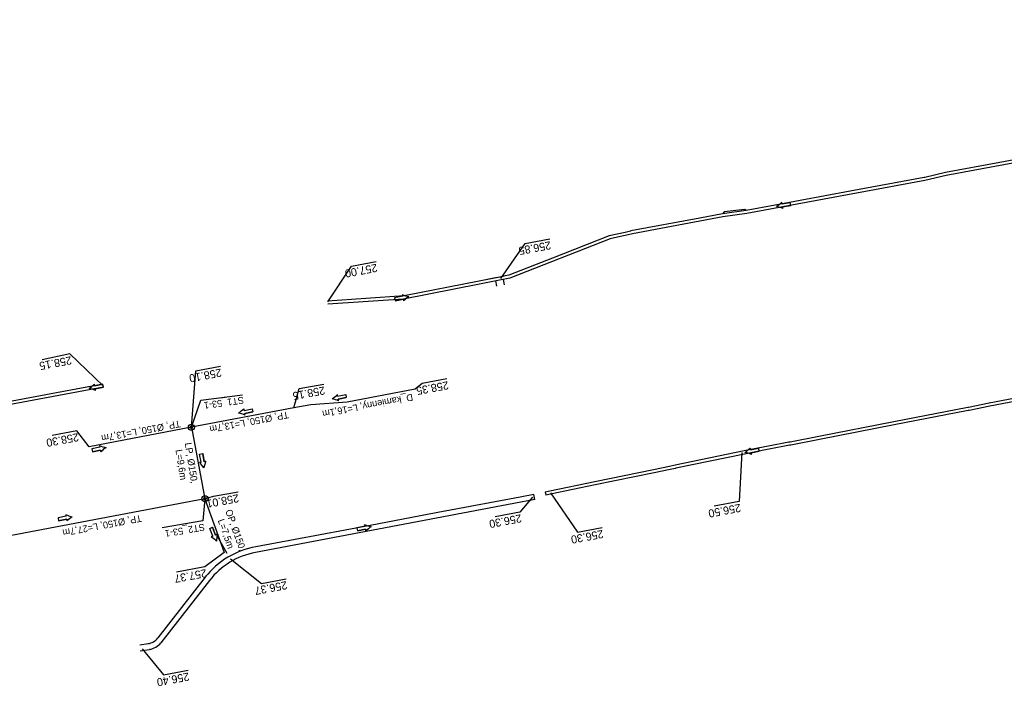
# Model space of a CAD drawing. Extents: x -1 to 65640748, y -22 to 5530284.
# Drawn here: x 6565167.7 to 6565296.8, y 5530114.9 to 5530202.4 of the extents above; entities that cross this region are included whole.
import ezdxf

# ---------------------------------------------------------------- set-up
doc = ezdxf.new("R2010")
doc.units = 0
for name, color, linetype in [('TOR_PS_ODW-drenaze', 7, 'Continuous'), ('TOR_PS_ODW-drenokolektory', 7, 'Continuous'), ('TOR_PS_ODW-kolektory', 7, 'Continuous'), ('TOR_PS_ODW-studnie PEHD', 7, 'Continuous'), ('TOR_PS_OPIS_O-opisy rurociagow', 7, 'Continuous'), ('TOR_PS_OPIS_O-opisy studni', 7, 'Continuous'), ('TOR_PS_OPIS_T-INFO', 7, 'Continuous'), ('TOR_PS_T-rowy otwarte umocnione', 7, 'Continuous')]:
    doc.layers.add(name, color=color, linetype=linetype)

msp = doc.modelspace()

# ---------------------------------------------------------------- linework, layer by layer
at = {"layer": 'TOR_PS_ODW-drenaze'}
for p, q in [((6565203.61, 5530151.46), (6565190.18, 5530148.92)), ((6565190.18, 5530148.92), (6565176.76, 5530146.37))]:
    msp.add_line(p, q, dxfattribs=at)
for points in [[(6565219.54, 5530153.92), (6565210.6, 5530152.23), (6565205.84, 5530151.88), (6565203.61, 5530151.46)], [(6565191.96, 5530139.54), (6565164.7, 5530134.37)]]:
    msp.add_lwpolyline(points, dxfattribs=at)
at = {"layer": 'TOR_PS_ODW-drenokolektory'}
msp.add_lwpolyline([(6565190.18, 5530148.92), (6565191.96, 5530139.54)], dxfattribs=at)
at = {"layer": 'TOR_PS_ODW-kolektory'}
msp.add_line((6565191.96, 5530139.54), (6565194.47, 5530132.49), dxfattribs=at)
at = {"layer": 'TOR_PS_ODW-studnie PEHD'}
for centre, radius in [((6565190.18, 5530148.92), 0.4), ((6565190.18, 5530148.92), 0.145), ((6565191.96, 5530139.54), 0.4), ((6565191.96, 5530139.54), 0.145)]:
    msp.add_circle(centre, radius, dxfattribs=at)
at = {"layer": 'TOR_PS_OPIS_O-opisy rurociagow'}
for p, q in [((6565268.71, 5530178.42), (6565267.64, 5530178.22)), ((6565267.64, 5530178.22), (6565268.71, 5530178.42)), ((6565267.71, 5530177.83), (6565268.78, 5530178.03)), ((6565267.71, 5530177.83), (6565268.78, 5530178.03)), ((6565268.78, 5530178.03), (6565268.71, 5530178.42)), ((6565268.78, 5530178.03), (6565268.71, 5530178.42)), ((6565217.9, 5530166.12), (6565216.83, 5530165.9)), ((6565217.9, 5530166.12), (6565216.83, 5530165.9)), ((6565216.83, 5530165.9), (6565216.91, 5530165.51)), ((6565216.83, 5530165.9), (6565216.91, 5530165.51)), ((6565216.91, 5530165.51), (6565217.98, 5530165.72)), ((6565217.98, 5530165.72), (6565216.91, 5530165.51)), ((6565178.56, 5530154.56), (6565177.49, 5530154.36)), ((6565177.49, 5530154.36), (6565178.56, 5530154.56)), ((6565177.56, 5530153.97), (6565178.64, 5530154.16)), ((6565177.56, 5530153.97), (6565178.64, 5530154.16)), ((6565178.64, 5530154.16), (6565178.56, 5530154.56)), ((6565178.64, 5530154.16), (6565178.56, 5530154.56)), ((6565209.35, 5530152.99), (6565210.43, 5530153.2)), ((6565209.35, 5530152.99), (6565210.43, 5530153.2)), ((6565210.5, 5530152.81), (6565209.43, 5530152.6)), ((6565209.43, 5530152.6), (6565210.5, 5530152.81)), ((6565210.43, 5530153.2), (6565210.5, 5530152.81)), ((6565210.43, 5530153.2), (6565210.5, 5530152.81)), ((6565197.09, 5530151.13), (6565198.16, 5530151.35)), ((6565197.09, 5530151.13), (6565198.16, 5530151.35)), ((6565198.24, 5530150.96), (6565197.17, 5530150.74)), ((6565197.17, 5530150.74), (6565198.24, 5530150.96)), ((6565198.16, 5530151.35), (6565198.24, 5530150.96)), ((6565198.16, 5530151.35), (6565198.24, 5530150.96)), ((6565178.19, 5530146.3), (6565177.12, 5530146.09)), ((6565178.19, 5530146.3), (6565177.12, 5530146.09)), ((6565177.12, 5530146.09), (6565177.19, 5530145.7)), ((6565177.12, 5530146.09), (6565177.19, 5530145.7)), ((6565177.19, 5530145.7), (6565178.26, 5530145.9)), ((6565178.26, 5530145.9), (6565177.19, 5530145.7)), ((6565191.26, 5530145.39), (6565191.66, 5530145.47)), ((6565191.26, 5530145.39), (6565191.66, 5530145.47)), ((6565191.47, 5530144.32), (6565191.26, 5530145.39)), ((6565191.47, 5530144.32), (6565191.26, 5530145.39)), ((6565191.66, 5530145.47), (6565191.86, 5530144.39)), ((6565191.86, 5530144.39), (6565191.66, 5530145.47)), ((6565264.58, 5530146.18), (6565263.5, 5530145.97)), ((6565263.5, 5530145.97), (6565264.58, 5530146.18)), ((6565263.58, 5530145.58), (6565264.65, 5530145.79)), ((6565263.58, 5530145.58), (6565264.65, 5530145.79)), ((6565264.65, 5530145.79), (6565264.58, 5530146.18)), ((6565264.65, 5530145.79), (6565264.58, 5530146.18)), ((6565173.76, 5530137.24), (6565172.69, 5530137.03)), ((6565173.76, 5530137.24), (6565172.69, 5530137.03)), ((6565172.69, 5530137.03), (6565172.76, 5530136.64)), ((6565172.69, 5530137.03), (6565172.76, 5530136.64)), ((6565172.76, 5530136.64), (6565173.83, 5530136.84)), ((6565173.83, 5530136.84), (6565172.76, 5530136.64)), ((6565212.95, 5530135.93), (6565211.88, 5530135.72)), ((6565212.95, 5530135.93), (6565211.88, 5530135.72)), ((6565192.58, 5530135.63), (6565192.95, 5530135.79)), ((6565192.58, 5530135.63), (6565192.95, 5530135.79)), ((6565192.99, 5530134.62), (6565192.58, 5530135.63)), ((6565192.99, 5530134.62), (6565192.58, 5530135.63)), ((6565192.95, 5530135.79), (6565193.36, 5530134.78)), ((6565193.36, 5530134.78), (6565192.95, 5530135.79)), ((6565211.88, 5530135.72), (6565211.95, 5530135.33)), ((6565211.88, 5530135.72), (6565211.95, 5530135.33)), ((6565211.95, 5530135.33), (6565213.03, 5530135.53)), ((6565213.03, 5530135.53), (6565211.95, 5530135.33))]:
    msp.add_line(p, q, dxfattribs=at)
for points in [[(6565267.61, 5530178.45), (6565267.61, 5530178.45)], [(6565267.76, 5530177.61), (6565267.76, 5530177.61)], [(6565217.85, 5530166.33), (6565217.85, 5530166.33)], [(6565218.01, 5530165.5), (6565218.01, 5530165.5)], [(6565177.46, 5530154.58), (6565177.46, 5530154.58)], [(6565177.61, 5530153.75), (6565177.61, 5530153.75)], [(6565209.32, 5530153.21), (6565209.32, 5530153.21)], [(6565209.49, 5530152.38), (6565209.49, 5530152.38)], [(6565197.05, 5530151.35), (6565197.05, 5530151.35)], [(6565197.22, 5530150.52), (6565197.22, 5530150.52)], [(6565178.14, 5530146.52), (6565178.14, 5530146.52)], [(6565178.3, 5530145.68), (6565178.3, 5530145.68)], [(6565263.47, 5530146.19), (6565263.47, 5530146.19)], [(6565263.63, 5530145.36), (6565263.63, 5530145.36)], [(6565191.25, 5530144.29), (6565191.25, 5530144.29)], [(6565192.08, 5530144.45), (6565192.08, 5530144.45)], [(6565173.71, 5530137.46), (6565173.71, 5530137.46)], [(6565173.87, 5530136.62), (6565173.87, 5530136.62)], [(6565212.9, 5530136.15), (6565212.9, 5530136.15)], [(6565193.56, 5530134.87), (6565193.56, 5530134.87)], [(6565213.06, 5530135.31), (6565213.06, 5530135.31)], [(6565192.78, 5530134.55), (6565192.78, 5530134.55)]]:
    msp.add_lwpolyline(points, dxfattribs=at)
for centre, radius, start, end in [((6565264.18, 5530181.97), 4.92, 303.8312, 314.213), ((6565264.18, 5530181.97), 4.92, 303.8312, 314.213), ((6565265.82, 5530173.09), 4.92, 66.7933, 77.1751), ((6565265.82, 5530173.09), 4.92, 66.7933, 77.1751), ((6565267.18, 5530178.28), 0.458, 353.6372, 22.0985), ((6565267.18, 5530178.28), 0.458, 353.6372, 22.0985), ((6565267.3, 5530177.62), 0.458, 358.9079, 27.3691), ((6565267.3, 5530177.62), 0.458, 358.9079, 27.3691), ((6565219.73, 5530170.88), 4.92, 247.4709, 257.8527), ((6565218.31, 5530166.33), 0.458, 179.5854, 208.0467), ((6565219.73, 5530170.88), 4.92, 247.4709, 257.8527), ((6565218.31, 5530166.33), 0.458, 179.5854, 208.0467), ((6565218.44, 5530165.68), 0.458, 174.3148, 202.776), ((6565218.44, 5530165.68), 0.458, 174.3148, 202.776), ((6565221.48, 5530162.02), 4.92, 124.5087, 134.8906), ((6565221.48, 5530162.02), 4.92, 124.5087, 134.8906), ((6565174.03, 5530158.11), 4.92, 303.8339, 314.2157), ((6565174.03, 5530158.11), 4.92, 303.8339, 314.2157), ((6565175.67, 5530149.23), 4.92, 66.796, 77.1778), ((6565175.67, 5530149.23), 4.92, 66.796, 77.1778), ((6565177.03, 5530154.41), 0.458, 353.6399, 22.1012), ((6565177.03, 5530154.41), 0.458, 353.6399, 22.1012), ((6565177.15, 5530153.75), 0.458, 358.9106, 27.3718), ((6565177.15, 5530153.75), 0.458, 358.9106, 27.3718), ((6565205.84, 5530156.68), 4.92, 304.7037, 315.0855), ((6565205.84, 5530156.68), 4.92, 304.7037, 315.0855), ((6565208.9, 5530153.03), 0.458, 354.5097, 22.9709), ((6565208.9, 5530153.03), 0.458, 354.5097, 22.9709), ((6565207.62, 5530147.83), 4.92, 67.6658, 78.0476), ((6565207.62, 5530147.83), 4.92, 67.6658, 78.0476), ((6565209.03, 5530152.38), 0.458, 359.7803, 28.2416), ((6565209.03, 5530152.38), 0.458, 359.7803, 28.2416), ((6565193.57, 5530154.83), 4.92, 304.7037, 315.0855), ((6565193.57, 5530154.83), 4.92, 304.7037, 315.0855), ((6565195.35, 5530145.97), 4.92, 67.6658, 78.0476), ((6565195.35, 5530145.97), 4.92, 67.6658, 78.0476), ((6565196.63, 5530151.18), 0.458, 354.5097, 22.9709), ((6565196.63, 5530151.18), 0.458, 354.5097, 22.9709), ((6565196.76, 5530150.52), 0.458, 359.7803, 28.2416), ((6565196.76, 5530150.52), 0.458, 359.7803, 28.2416), ((6565180.06, 5530151.04), 4.92, 247.0234, 257.4052), ((6565178.6, 5530146.51), 0.458, 179.1379, 207.5992), ((6565180.06, 5530151.04), 4.92, 247.0234, 257.4052), ((6565178.6, 5530146.51), 0.458, 179.1379, 207.5992), ((6565178.72, 5530145.86), 0.458, 173.8673, 202.3285), ((6565178.72, 5530145.86), 0.458, 173.8673, 202.3285), ((6565181.74, 5530142.17), 4.92, 124.0613, 134.4431), ((6565181.74, 5530142.17), 4.92, 124.0613, 134.4431), ((6565260.01, 5530149.69), 4.92, 304.3196, 314.7014), ((6565260.01, 5530149.69), 4.92, 304.3196, 314.7014), ((6565261.74, 5530140.82), 4.92, 67.2817, 77.6635), ((6565261.74, 5530140.82), 4.92, 67.2817, 77.6635), ((6565263.05, 5530146.02), 0.458, 354.1256, 22.5869), ((6565263.05, 5530146.02), 0.458, 354.1256, 22.5869), ((6565263.18, 5530145.36), 0.458, 359.3963, 27.8575), ((6565263.18, 5530145.36), 0.458, 359.3963, 27.8575), ((6565191.42, 5530143.86), 0.458, 84.0612, 112.5225), ((6565191.42, 5530143.86), 0.458, 84.0612, 112.5225), ((6565187.75, 5530140.83), 4.92, 34.2552, 44.637), ((6565187.75, 5530140.83), 4.92, 34.2552, 44.637), ((6565196.62, 5530142.54), 4.92, 157.2173, 167.5991), ((6565196.62, 5530142.54), 4.92, 157.2173, 167.5991), ((6565192.08, 5530143.99), 0.458, 89.3319, 117.7931), ((6565192.08, 5530143.99), 0.458, 89.3319, 117.7931), ((6565175.63, 5530141.98), 4.92, 247.0234, 257.4052), ((6565174.17, 5530137.45), 0.458, 179.1379, 207.5992), ((6565175.63, 5530141.98), 4.92, 247.0234, 257.4052), ((6565174.17, 5530137.45), 0.458, 179.1379, 207.5992), ((6565174.29, 5530136.8), 0.458, 173.8673, 202.3285), ((6565174.29, 5530136.8), 0.458, 173.8673, 202.3285), ((6565177.31, 5530133.11), 4.92, 124.0613, 134.4431), ((6565177.31, 5530133.11), 4.92, 124.0613, 134.4431), ((6565214.82, 5530140.67), 4.92, 246.9669, 257.3487), ((6565213.36, 5530136.14), 0.458, 179.0814, 207.5427), ((6565214.82, 5530140.67), 4.92, 246.9669, 257.3487), ((6565213.36, 5530136.14), 0.458, 179.0814, 207.5427), ((6565193.65, 5530134.42), 0.458, 100.7282, 129.1895), ((6565193.65, 5530134.42), 0.458, 100.7282, 129.1895), ((6565198.39, 5530133.9), 4.92, 168.6137, 178.9955), ((6565198.39, 5530133.9), 4.92, 168.6137, 178.9955), ((6565213.48, 5530135.48), 0.458, 173.8108, 202.272), ((6565213.48, 5530135.48), 0.458, 173.8108, 202.272), ((6565216.5, 5530131.8), 4.92, 124.0048, 134.3866), ((6565216.5, 5530131.8), 4.92, 124.0048, 134.3866), ((6565193.03, 5530134.17), 0.458, 95.4576, 123.9188), ((6565193.03, 5530134.17), 0.458, 95.4576, 123.9188), ((6565190.03, 5530130.47), 4.92, 45.6516, 56.0334), ((6565190.03, 5530130.47), 4.92, 45.6516, 56.0334)]:
    msp.add_arc(centre, radius, start, end, dxfattribs=at)
at = {"layer": 'TOR_PS_OPIS_T-INFO'}
for points in [[(6565230.77, 5530168.44), (6565233.96, 5530173.04), (6565237.2, 5530173.64)], [(6565208.07, 5530165.36), (6565211.19, 5530170.07), (6565214.42, 5530170.67)], [(6565178.6, 5530154.36), (6565174.24, 5530158.54), (6565170.59, 5530157.78)], [(6565190.18, 5530148.92), (6565190.76, 5530156.32), (6565194, 5530156.93)], [(6565203.61, 5530151.46), (6565204.33, 5530153.99), (6565207.56, 5530154.59)], [(6565223.68, 5530155.26), (6565223.68, 5530155.26), (6565220.45, 5530154.64), (6565219.54, 5530153.92)], [(6565190.18, 5530148.92), (6565191.4, 5530152.49), (6565196.9, 5530153.19)], [(6565176.76, 5530146.37), (6565175.17, 5530148.46), (6565171.93, 5530147.83)], [(6565262.36, 5530145.59), (6565262, 5530139.17), (6565258.76, 5530138.55)], [(6565191.96, 5530139.54), (6565193.1, 5530139.86), (6565196.33, 5530140.46)], [(6565237.27, 5530140.31), (6565240.83, 5530135.16), (6565244.07, 5530135.76)], [(6565191.96, 5530139.54), (6565191.66, 5530136.64), (6565186.35, 5530135.74)], [(6565234.9, 5530139.73), (6565233.25, 5530137.8), (6565230.01, 5530137.18)], [(6565194.47, 5530132.49), (6565191.96, 5530130.61), (6565188.21, 5530129.89)], [(6565195.32, 5530131.65), (6565199.36, 5530128.43), (6565202.59, 5530129.04)], [(6565183.71, 5530119.87), (6565186.51, 5530116.44), (6565189.75, 5530117.04)]]:
    msp.add_lwpolyline(points, dxfattribs=at)
at = {"layer": 'TOR_PS_T-rowy otwarte umocnione'}
for p, q in [((6565231.23, 5530167.61), (6565231.1, 5530168.31)), ((6565230.25, 5530167.42), (6565230.11, 5530168.12)), ((6565191.96, 5530139.54), (6565194.47, 5530132.49)), ((6565192, 5530129.25), (6565185.78, 5530121.28)), ((6565192.55, 5530128.82), (6565186.18, 5530120.64)), ((6565183.41, 5530120.37), (6565184.49, 5530120.53)), ((6565183.47, 5530119.58), (6565184.69, 5530119.78))]:
    msp.add_line(p, q, dxfattribs=at)
for points in [[(6565414.79, 5530202.39), (6565404.96, 5530200.55), (6565331.19, 5530186.87), (6565304.42, 5530184.64), (6565304.32, 5530184.62), (6565301.45, 5530184.22), (6565289.18, 5530181.94), (6565286.35, 5530181.29), (6565263.03, 5530176.96), (6565259.89, 5530176.51), (6565248.03, 5530174.31), (6565248.02, 5530174.3), (6565245.09, 5530173.64), (6565231.94, 5530168.47), (6565230.36, 5530168.16)], [(6565301.38, 5530184.61), (6565296.2, 5530183.65), (6565289.09, 5530182.34), (6565286.39, 5530181.71), (6565286.27, 5530181.68), (6565276.56, 5530179.88), (6565266.73, 5530178.06), (6565262.96, 5530177.36), (6565259.82, 5530176.91), (6565256.87, 5530176.36), (6565247.8, 5530174.68), (6565247.78, 5530174.66), (6565247.05, 5530174.49), (6565244.97, 5530174.02), (6565237.52, 5530171.09), (6565231.83, 5530168.86), (6565231.34, 5530168.77), (6565230.85, 5530168.67), (6565227.91, 5530168.09), (6565218.09, 5530166.15), (6565208.02, 5530165.46)], [(6565301.38, 5530184.61), (6565296.2, 5530183.65), (6565289.09, 5530182.34), (6565286.39, 5530181.71), (6565286.27, 5530181.68), (6565276.56, 5530179.88), (6565266.73, 5530178.06), (6565262.96, 5530177.36), (6565262.91, 5530177.39), (6565262.77, 5530177.49), (6565260.04, 5530177.19), (6565259.82, 5530176.91), (6565256.87, 5530176.36), (6565247.8, 5530174.68), (6565247.78, 5530174.66), (6565247.05, 5530174.49), (6565244.97, 5530174.02), (6565237.52, 5530171.09), (6565231.83, 5530168.86), (6565231.34, 5530168.77), (6565230.85, 5530168.67), (6565230.77, 5530168.66)], [(6565230.28, 5530168.56), (6565227.91, 5530168.09), (6565218.09, 5530166.15)], [(6565230.36, 5530168.16), (6565227.98, 5530167.7), (6565217.98, 5530165.72), (6565208.07, 5530165.06)], [(6565178.56, 5530154.56), (6565169.71, 5530152.92), (6565159.88, 5530151.09), (6565153, 5530149.82), (6565143.28, 5530147.27)], [(6565178.64, 5530154.16), (6565153.07, 5530149.42), (6565143.38, 5530146.88)], [(6565301.93, 5530153.44), (6565294.83, 5530152.06), (6565292.11, 5530151.53), (6565291.99, 5530151.51), (6565282.3, 5530149.62), (6565272.48, 5530147.72), (6565268.72, 5530146.98), (6565268.68, 5530146.98), (6565268.55, 5530146.95), (6565265.87, 5530146.43), (6565265.61, 5530146.38), (6565262.66, 5530145.81), (6565253.63, 5530143.93), (6565253.61, 5530143.93), (6565252.87, 5530143.77), (6565250.79, 5530143.34), (6565243.08, 5530141.74), (6565237.2, 5530140.52), (6565236.56, 5530140.39), (6565236.65, 5530140)], [(6565302, 5530153.05), (6565294.91, 5530151.67), (6565292.19, 5530151.14), (6565292.06, 5530151.11), (6565282.37, 5530149.23), (6565272.55, 5530147.32), (6565268.8, 5530146.59), (6565268.75, 5530146.58), (6565268.63, 5530146.56), (6565265.95, 5530146.04), (6565265.68, 5530145.99), (6565262.74, 5530145.41), (6565253.7, 5530143.54), (6565253.68, 5530143.53), (6565252.95, 5530143.38), (6565250.86, 5530142.95), (6565243.15, 5530141.35), (6565237.28, 5530140.13), (6565236.65, 5530140)], [(6565235.23, 5530139.46), (6565235.09, 5530140.11), (6565233.28, 5530139.76), (6565223.45, 5530137.9), (6565223.44, 5530137.9), (6565213.62, 5530136.05), (6565203.8, 5530134.19), (6565198.65, 5530133.22)], [(6565235.23, 5530139.46), (6565233.4, 5530139.1), (6565198.57, 5530132.5)], [(6565193.5, 5530134.74), (6565194.83, 5530132.39)]]:
    msp.add_lwpolyline(points, dxfattribs=at)
for centre, radius, start, end in [((6565200.44, 5530122.67), 10.7, 99.6394, 142.0546), ((6565200.44, 5530122.67), 10, 100.7401, 142.0546), ((6565184.21, 5530122.51), 2, 278.1904, 322.0546), ((6565184.36, 5530122.06), 2.3, 278.1904, 322.0546)]:
    msp.add_arc(centre, radius, start, end, dxfattribs=at)

# ---------------------------------------------------------------- texts
at = {"layer": 'TOR_PS_OPIS_O-opisy rurociagow'}
for s, rotation, p in [('D_kamienny, L=16,1m', 190.5985, (6565219.15, 5530153.31)), ('TP, Ø150, L=13,7m', 190.5985, (6565202.85, 5530151.01)), ('TP, Ø150, L=13,7m', 190.5985, (6565188.66, 5530149.83)), ('LP, Ø150, ', 278.9305, (6565189.31, 5530146.84)), ('L=9,6m', 278.9305, (6565188.09, 5530145.94)), ('TP, Ø150, L=27,7m', 190.5985, (6565183.57, 5530137.43)), ('OP, Ø150, ', 289.7202, (6565194.61, 5530137.95)), ('L=7,5m', 289.7202, (6565193.62, 5530136.7))]:
    msp.add_text(s, height=0.9, rotation=rotation, dxfattribs=at).set_placement(p)
at = {"layer": 'TOR_PS_OPIS_O-opisy studni'}
for s, rotation, p in [('ST1_53-1', 187.8879, (6565197, 5530152.93)), ('ST2_53-1', 189.7733, (6565191.85, 5530136.28))]:
    msp.add_text(s, height=0.9, rotation=rotation, dxfattribs=at).set_placement(p)
at = {"layer": 'TOR_PS_OPIS_T-INFO'}
for s, rotation, p in [('256.85', 190.7506, (6565237.24, 5530173.34)), ('257.00', 190.7506, (6565214.46, 5530170.37)), ('258.15', 190.7159, (6565174.38, 5530158.24)), ('258.10', 190.7506, (6565194.03, 5530156.62)), ('258.15', 190.7506, (6565207.6, 5530154.29)), ('258.35', 190.7159, (6565223.81, 5530154.97)), ('258.30', 190.7159, (6565175.3, 5530148.16)), ('258.01', 190.7506, (6565196.3, 5530140.15)), ('256.50', 190.7159, (6565262.13, 5530138.88)), ('256.30', 190.7159, (6565233.38, 5530137.51)), ('256.30', 190.7506, (6565244.11, 5530135.46)), ('257.37', 190.7159, (6565192.09, 5530130.32)), ('256.37', 190.7506, (6565202.63, 5530128.74)), ('256.40', 190.7506, (6565189.79, 5530116.74))]:
    msp.add_text(s, height=1.05, rotation=rotation, dxfattribs=at).set_placement(p)

doc.saveas('drawing.dxf')
